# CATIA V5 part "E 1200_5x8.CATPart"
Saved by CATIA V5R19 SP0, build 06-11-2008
Definition: E 1200_5x8
Nomenclature: E 1200_5x8
Description: PART--DESC
Material "Steel": density 7860 kg/m3, Young's modulus 2e+11 Pa, Poisson ratio 0.266, thermal expansion 1.17e-05 1/K
Bounding box of the stored display mesh (mm): x -4.24 to 4.24, y -4.25 to 4.25, z 30.5 to 43.5
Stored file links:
  G:\UTB\Kombinované\Bakalářská práce\Catia\FORMA\E 1200_5x8.CATPart
  D:\Aplikace\CATIA\Nová složka\win_b64\startup\materials\Catalog.CATMaterial
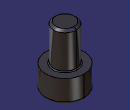
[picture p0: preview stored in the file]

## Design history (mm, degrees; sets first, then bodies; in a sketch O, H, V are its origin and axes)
Body1 "E 1200_5x8" (main body)
  Solid1: solid without history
